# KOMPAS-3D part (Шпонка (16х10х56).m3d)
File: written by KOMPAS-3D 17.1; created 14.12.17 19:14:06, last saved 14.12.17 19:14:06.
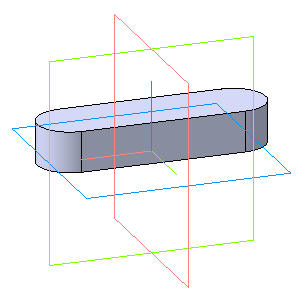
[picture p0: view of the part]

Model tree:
1. Операция без истории:1  (labels: Шпонка (16х10х56))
